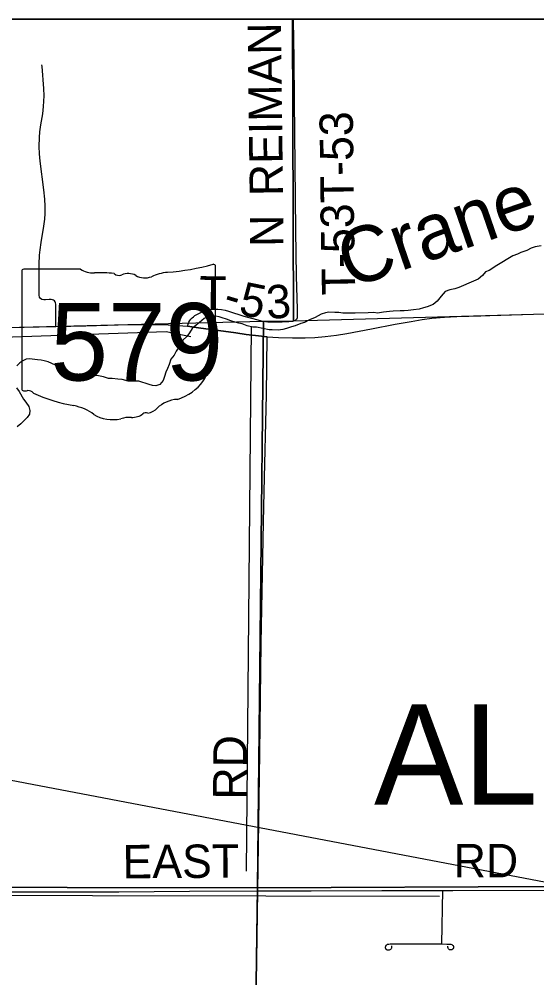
# Model space of a CAD drawing. Extents: x 0 to 34, y 0 to 22.
# Drawn here: x 6.247 to 7.128, y 19.268 to 20.9 of the extents above; entities that cross this region are included whole.
import ezdxf

# ---------------------------------------------------------------- set-up
doc = ezdxf.new("R2010")
doc.units = 0
for name, color, linetype in [('Default', 7, 'Continuous'), ('GM_X_County_Road', 7, 'Continuous'), ('GM_X_County_Road_Text', 7, 'Continuous'), ('GM_X_Interstate_Route', 7, 'Continuous'), ('GM_X_Major_River', 7, 'Continuous'), ('GM_X_Major_River_Text', 7, 'Continuous'), ('GM_X_Minor_River', 7, 'Continuous'), ('GM_X_Section', 7, 'Continuous'), ('GM_X_State_Location', 7, 'Continuous'), ('GM_X_State_Route', 7, 'Continuous'), ('GM_X_State_Shield', 7, 'Continuous'), ('GM_X_Township_Road', 7, 'Continuous'), ('GM_X_Township_Road_Text', 7, 'Continuous'), ('GM_X_Township_Text', 7, 'Continuous'), ('SH_Data', 7, 'Continuous'), ('SH_Text', 7, 'Continuous')]:
    doc.layers.add(name, color=color, linetype=linetype)

msp = doc.modelspace()

# ---------------------------------------------------------------- linework, layer by layer
at = {"layer": 'Default'}
for points in [[(6.7117, 20.9), (5.7199, 20.9), (5.7161, 20.3629), (6.6624, 20.3857), (6.7136, 20.3867)], [(7.7257, 20.9), (6.7117, 20.9), (6.7136, 20.3867), (7.6743, 20.413), (7.7236, 20.4137)]]:
    msp.add_lwpolyline(points, close=True, dxfattribs=at)
at = {"layer": 'GM_X_County_Road'}
for points in [[(6.9678, 19.4166), (6.9849, 19.4166), (7.1776, 19.4172), (7.3674, 19.4198), (7.5661, 19.4229), (7.5971, 19.4234), (7.6537, 19.424), (7.6641, 19.424)], [(5.6777, 19.4164), (5.7963, 19.4156), (5.9207, 19.4153), (6.0476, 19.4147), (6.1657, 19.4142), (6.2928, 19.4144), (6.4163, 19.4146), (6.5366, 19.4158), (6.6531, 19.4163)], [(6.6531, 19.4163), (6.7438, 19.4163), (6.8642, 19.4166), (6.9678, 19.4166)]]:
    msp.add_lwpolyline(points, dxfattribs=at)
at = {"layer": 'GM_X_Interstate_Route'}
msp.add_lwpolyline([(8.9, 17.3895), (8.9, 20.9), (4.7088, 20.9), (4.7053, 20.5025), (4.7052, 20.3461), (4.7052, 20.3382), (4.7052, 20.2636), (4.7052, 20.2455), (4.7051, 20.2077), (4.7051, 20.1455), (4.7053, 20.0088), (4.7051, 19.9497), (4.7052, 19.9217), (4.7054, 19.8814), (4.7049, 19.8162), (4.7051, 19.726), (4.7054, 19.4463), (4.7058, 19.4215), (4.706, 19.4081), (4.7064, 19.3593), (4.7066, 19.3437), (4.7069, 19.3065), (4.7068, 19.2692), (4.7066, 19.2071)], dxfattribs=at)
at = {"layer": 'GM_X_Major_River'}
for points in [[(7.135, 20.5144), (7.1248, 20.5122), (7.118, 20.5099), (7.1111, 20.5062), (7.1009, 20.5028), (7.0948, 20.5002), (7.0872, 20.4972), (7.0598, 20.4806), (7.0465, 20.472), (7.0405, 20.4701), (7.0351, 20.4637), (7.0279, 20.4576), (7.0199, 20.4539), (6.9949, 20.4434), (6.988, 20.4411), (6.9797, 20.4393), (6.9721, 20.4363), (6.9649, 20.4283), (6.9584, 20.42), (6.9515, 20.4144), (6.9409, 20.4103), (6.9348, 20.4088), (6.9276, 20.4065), (6.9178, 20.4054), (6.9087, 20.404), (6.9022, 20.4036), (6.895, 20.4033), (6.8833, 20.403), (6.8772, 20.4022), (6.8666, 20.4015), (6.8567, 20.3997), (6.8503, 20.4008), (6.8408, 20.4001), (6.8186, 20.3998)], [(6.8186, 20.3998), (6.804, 20.3994), (6.7975, 20.3994), (6.7907, 20.4005), (6.7842, 20.4009), (6.774, 20.4013), (6.7683, 20.4001), (6.7607, 20.3979), (6.7505, 20.3922), (6.7406, 20.388), (6.7323, 20.3838), (6.7262, 20.3819), (6.7163, 20.3777), (6.7102, 20.3762), (6.7019, 20.3732), (6.6954, 20.3717), (6.6875, 20.3705), (6.6776, 20.3709), (6.6723, 20.3713), (6.6617, 20.3732), (6.6507, 20.3755), (6.6442, 20.3759), (6.6347, 20.3778), (6.626, 20.3812), (6.6207, 20.3823), (6.6143, 20.3842), (6.6067, 20.3865), (6.5995, 20.3892), (6.5922, 20.3914), (6.5869, 20.3933), (6.5809, 20.3945), (6.5744, 20.3949), (6.568, 20.3941), (6.5615, 20.3903), (6.5535, 20.3839), (6.5482, 20.3793), (6.5414, 20.3732), (6.5368, 20.366), (6.5319, 20.3599), (6.5255, 20.3535), (6.5209, 20.3466), (6.5171, 20.3402), (6.5137, 20.3349), (6.5103, 20.328), (6.505, 20.3212), (6.5019, 20.3121), (6.4989, 20.3056), (6.4962, 20.2991), (6.4943, 20.2916), (6.4917, 20.2847), (6.486, 20.2779), (6.4795, 20.2756), (6.4738, 20.2764), (6.4678, 20.2783), (6.4503, 20.2836), (6.4321, 20.2836), (6.4222, 20.2866), (6.4146, 20.287), (6.4052, 20.2881), (6.3987, 20.2885), (6.3904, 20.2912), (6.3816, 20.2931), (6.3721, 20.2942), (6.3668, 20.2942), (6.3611, 20.2935), (6.3554, 20.2935), (6.3501, 20.2931), (6.3376, 20.2931), (6.3308, 20.2973), (6.3255, 20.3026), (6.3156, 20.3087), (6.3084, 20.311), (6.302, 20.314), (6.2959, 20.3167), (6.2894, 20.3186), (6.2841, 20.3193), (6.2781, 20.3201), (6.2644, 20.3216), (6.2587, 20.3212), (6.253, 20.3186), (6.2477, 20.3151), (6.2424, 20.3098)], [(6.242, 20.2722), (6.2469, 20.2661), (6.2538, 20.2532), (6.2579, 20.2479), (6.2629, 20.2407), (6.2647, 20.2338), (6.2644, 20.2274), (6.2602, 20.2221), (6.2545, 20.216), (6.2492, 20.2114), (6.2431, 20.2061)]]:
    msp.add_lwpolyline(points, dxfattribs=at)
at = {"layer": 'GM_X_Minor_River'}
for points in [[(5.6979, 20.9), (5.6949, 20.3407), (6.497, 20.3683), (6.5391, 20.3599)], [(6.6413, 20.3764), (6.6333, 19.4497)], [(6.9619, 19.4063), (5.4848, 19.4092)]]:
    msp.add_lwpolyline(points, dxfattribs=at)
at = {"layer": 'GM_X_Section'}
for points in [[(7.6743, 20.413), (7.6545, 19.4258), (6.6525, 19.4215), (6.6624, 20.3857), (6.7136, 20.3867)], [(6.6624, 20.3857), (6.6525, 19.4215), (5.6799, 19.4229), (5.6885, 20.3628), (5.7161, 20.3629)], [(5.6799, 19.4229), (6.6525, 19.4215), (6.6382, 18.4059), (5.6682, 18.408)], [(7.6545, 19.4258), (7.6481, 18.4165), (6.6382, 18.4059), (6.6525, 19.4215)]]:
    msp.add_lwpolyline(points, close=True, dxfattribs=at)
at = {"layer": 'GM_X_State_Route'}
for points in [[(7.0328, 20.3951), (7.0479, 20.3956), (7.159, 20.399), (7.2196, 20.4008), (7.3361, 20.4034), (7.4704, 20.4063), (7.6226, 20.4091), (7.6767, 20.4104), (7.7258, 20.4115)], [(6.6686, 20.359), (6.6883, 20.358), (6.7121, 20.3574), (6.7335, 20.3576), (6.7499, 20.3583), (6.7675, 20.36), (6.7871, 20.3623), (6.8044, 20.365), (6.8467, 20.373), (6.8868, 20.3806), (6.9138, 20.3856), (6.9326, 20.3886), (6.9492, 20.3908), (6.9709, 20.3926), (6.9915, 20.3938), (7.0328, 20.3951)], [(5.7156, 20.365), (5.8647, 20.3682), (6.0052, 20.3707), (6.1521, 20.3737), (6.306, 20.3769), (6.3093, 20.3769), (6.3599, 20.378), (6.4339, 20.38), (6.4792, 20.3805), (6.5002, 20.3799), (6.5174, 20.3787), (6.5333, 20.3772)], [(6.5333, 20.3772), (6.5519, 20.3748), (6.6157, 20.3658), (6.6332, 20.3633), (6.6539, 20.3607), (6.6686, 20.359)]]:
    msp.add_lwpolyline(points, dxfattribs=at)
at = {"layer": 'GM_X_State_Shield'}
for p, q in [((6.2512, 20.4709), (6.2512, 20.2708)), ((6.351, 20.4744), (6.2544, 20.4744)), ((6.5808, 20.3746), (6.5808, 20.4793)), ((6.5807, 20.3747), (6.5808, 20.3746))]:
    msp.add_line(p, q, dxfattribs=at)
for centre, major_axis, start_param, end_param in [((6.4634, 20.7472), (0.3495, 0), 4.814394, 5.042369), ((6.5771, 20.4798), (0.00367, 0), 6.141152, 7.989035), ((6.255, 20.4713), (0.00382, 0), 1.712693, 3.28349), ((6.374, 20.4976), (0.037, 0), 4.042523, 4.731795), ((6.3862, 20.362), (0.133, 0), 1.404758, 1.657858), ((6.4164, 20.4724), (0.0107, 0), 3.836095, 5.185415), ((6.4321, 20.4493), (0.0222, 0), 0.950623, 2.079405), ((6.508, 20.4132), (0.0703, 0), 1.699011, 2.107814), ((6.4608, 20.481), (0.0267, 0), 4.081561, 5.145723), ((6.5799, 20.367), (0.00568, 0), 1.883978, 3.671073), ((6.5769, 20.3742), (0.00393, 0), 5.05454, 6.418171), ((6.5438, 20.3537), (0.0341, 0), 5.934695, 6.695948), ((6.5939, 20.3308), (0.0248, 0), 2.387724, 3.262537), ((6.483, 20.3175), (0.0874, 0), 5.101752, 6.440018), ((6.255, 20.2704), (0.00385, 0), 3.00124, 4.508301), ((6.2556, 20.2908), (0.0294, 0), 4.665946, 4.897461), ((6.2616, 20.2593), (0.0106, 0), 0.519207, 1.627899), ((6.3954, 20.4391), (0.2524, 0), 4.195997, 4.488961), ((6.5198, 20.2146), (0.0479, 0), 1.647645, 2.488434), ((6.3202, 20.1809), (0.079, 0), 0.823519, 1.323587), ((6.4592, 20.2514), (0.0282, 0), 4.937069, 5.64225), ((6.4056, 20.2583), (0.0501, 0), 4.026481, 4.996735), ((6.4345, 20.1891), (0.0412, 0), 1.495662, 1.94098), ((6.4382, 20.2433), (0.0267, 0), 4.691044, 5.507374), ((6.4624, 20.2239), (0.00752, 0), 1.147584, 2.315152)]:
    msp.add_ellipse(centre, major_axis=major_axis, ratio=0.8, start_param=start_param, end_param=end_param, dxfattribs=at)
at = {"layer": 'GM_X_Township_Road'}
msp.add_line((6.9662, 19.3257), (6.9678, 19.4166), dxfattribs=at)
for points in [[(6.719, 20.3892), (6.7196, 20.39), (6.7201, 20.3908), (6.7204, 20.3917), (6.7205, 20.3926), (6.7206, 20.3942), (6.7202, 20.4065), (6.7186, 20.4625), (6.7178, 20.5402), (6.7154, 20.7609), (6.7146, 20.8324), (6.7139, 20.8976), (6.7139, 20.9)], [(6.3093, 20.3769), (6.3093, 20.3795), (6.3093, 20.3803), (6.3091, 20.3993), (6.309, 20.4117), (6.3088, 20.4149), (6.3083, 20.4173), (6.3078, 20.4189), (6.3065, 20.4203), (6.305, 20.4214), (6.3032, 20.4222), (6.301, 20.4226), (6.2979, 20.4227), (6.2916, 20.4223), (6.2885, 20.4224), (6.2854, 20.4229), (6.2829, 20.4245), (6.2813, 20.427), (6.2806, 20.4299), (6.2806, 20.4374), (6.2807, 20.4518), (6.2805, 20.4704), (6.2806, 20.4828), (6.2814, 20.4983), (6.2823, 20.5076), (6.2841, 20.5199), (6.2887, 20.5474), (6.2902, 20.5597), (6.2908, 20.569), (6.2908, 20.5814), (6.2902, 20.5938), (6.2886, 20.6093), (6.2822, 20.6585), (6.2812, 20.6709), (6.2809, 20.6833), (6.2813, 20.6988), (6.282, 20.7081), (6.2837, 20.7204), (6.2868, 20.7388), (6.2883, 20.7511), (6.2889, 20.7604), (6.2891, 20.7697), (6.2886, 20.7821), (6.2856, 20.8192), (6.2852, 20.8223)], [(6.5333, 20.3772), (6.5343, 20.3809), (6.5356, 20.3843), (6.5369, 20.3869), (6.5387, 20.3892), (6.541, 20.3916), (6.5432, 20.3935), (6.5458, 20.3953), (6.5489, 20.3971), (6.5536, 20.3997), (6.5592, 20.4022), (6.5648, 20.4041), (6.5699, 20.4054), (6.5726, 20.4059), (6.5754, 20.4063), (6.5787, 20.4065), (6.5848, 20.4064), (6.5911, 20.4059), (6.5971, 20.4046), (6.6032, 20.4028), (6.629, 20.3946), (6.6527, 20.3879), (6.6586, 20.3866), (6.6657, 20.3853), (6.67, 20.3849), (6.6739, 20.3846), (6.6801, 20.3845), (6.6941, 20.385), (6.7059, 20.3856)], [(6.7059, 20.3856), (6.7088, 20.3858), (6.7123, 20.3861), (6.7144, 20.3865), (6.7159, 20.387), (6.7172, 20.3876), (6.7183, 20.3885), (6.719, 20.3892)], [(6.6686, 20.359), (6.6539, 20.3607), (6.6332, 20.3633), (6.6157, 20.3658), (6.5519, 20.3748), (6.5333, 20.3772)], [(6.6531, 19.4163), (6.6564, 19.6513), (6.6588, 19.8378), (6.6625, 20.043), (6.6635, 20.0958), (6.6674, 20.2605), (6.6686, 20.359)], [(6.641, 18.403), (6.6414, 18.4637), (6.6419, 18.5601), (6.6428, 18.7373), (6.6435, 18.8121), (6.644, 18.8648), (6.6455, 18.955), (6.649, 19.1653), (6.6493, 19.1819), (6.6531, 19.4163)], [(6.8807, 19.3224), (6.8807, 19.3205), (6.8804, 19.3187), (6.8798, 19.3173), (6.8788, 19.3161), (6.8777, 19.3155), (6.8763, 19.3151), (6.8747, 19.3151), (6.8731, 19.3154), (6.8719, 19.3161), (6.8711, 19.317), (6.8706, 19.3179), (6.8704, 19.3188), (6.8703, 19.3203), (6.8707, 19.3219), (6.8714, 19.3234), (6.8726, 19.3244), (6.8739, 19.3251), (6.8758, 19.3255), (6.878, 19.3257), (6.8846, 19.3259), (6.9662, 19.3257)], [(6.9662, 19.3257), (6.9746, 19.3254), (6.9782, 19.3253), (6.9814, 19.3252), (6.983, 19.3248), (6.9844, 19.3239), (6.9852, 19.3229), (6.9858, 19.3216), (6.986, 19.3201), (6.9858, 19.3189), (6.9853, 19.3177), (6.9844, 19.3166), (6.9832, 19.3159), (6.9817, 19.3155), (6.9803, 19.3156), (6.9792, 19.316), (6.9782, 19.3166), (6.9775, 19.3174), (6.9767, 19.3185), (6.9762, 19.3201), (6.9762, 19.3217)]]:
    msp.add_lwpolyline(points, dxfattribs=at)
at = {"layer": 'SH_Data'}
msp.add_line((2.1, 20.9), (8.9, 20.9), dxfattribs=at)
at = {"layer": 'SH_Text'}
msp.add_lwpolyline([(9.2181, 19.0346), (2.1904, 20.3744), (9.2181, 18.3428)], close=True, dxfattribs=at)

# ---------------------------------------------------------------- texts
at = {"layer": 'GM_X_County_Road_Text'}
for s, rotation, p in [('EAST', 0.2762, (6.4227, 19.4375)), ('RD', 0, (6.9863, 19.4392))]:
    msp.add_text(s, height=0.05682, rotation=rotation, dxfattribs=at).set_placement(p)
at = {"layer": 'GM_X_Major_River_Text'}
msp.add_text('Crane ', height=0.09476, rotation=19.0282, dxfattribs=at).set_placement((6.8091, 20.441))
at = {"layer": 'GM_X_State_Location'}
for s in ['s', 'r']:
    msp.add_text(s, height=0.000189, dxfattribs=at).set_placement((6.4123, 20.3576))
msp.add_text('579', height=0.000189, rotation=0, dxfattribs=at).set_placement((6.3454, 20.3438))
at = {"layer": 'GM_X_State_Shield'}
msp.add_text('579', height=0.13184, dxfattribs=at).set_placement((6.2997, 20.2849))
at = {"layer": 'GM_X_Township_Road_Text'}
for s, height, rotation, p in [('REIMAN', 0.05682, 90.6763, (6.6958, 20.5991)), ('T-53', 0.05682, 90.7083, (6.8165, 20.5872)), ('T-53', 0.05682, 91.0657, (6.819, 20.4306)), ('N', 0.0568, 90.5786, (6.6966, 20.5126)), ('T', 0.0568, 359.1264, (6.5528, 20.4059)), ('5', 0.0568, 348.3386, (6.6185, 20.3979)), ('3', 0.0568, 3.3288, (6.6686, 20.3897)), ('-', 0.0568, 343.3186, (6.5911, 20.4059)), ('RD', 0.05682, 89.5063, (6.6333, 19.5712))]:
    msp.add_text(s, height=height, rotation=rotation, dxfattribs=at).set_placement(p)
at = {"layer": 'GM_X_Township_Text'}
msp.add_text('ALLEN', height=0.17045, rotation=0, dxfattribs=at).set_placement((6.8508, 19.5631))

doc.saveas('drawing.dxf')
